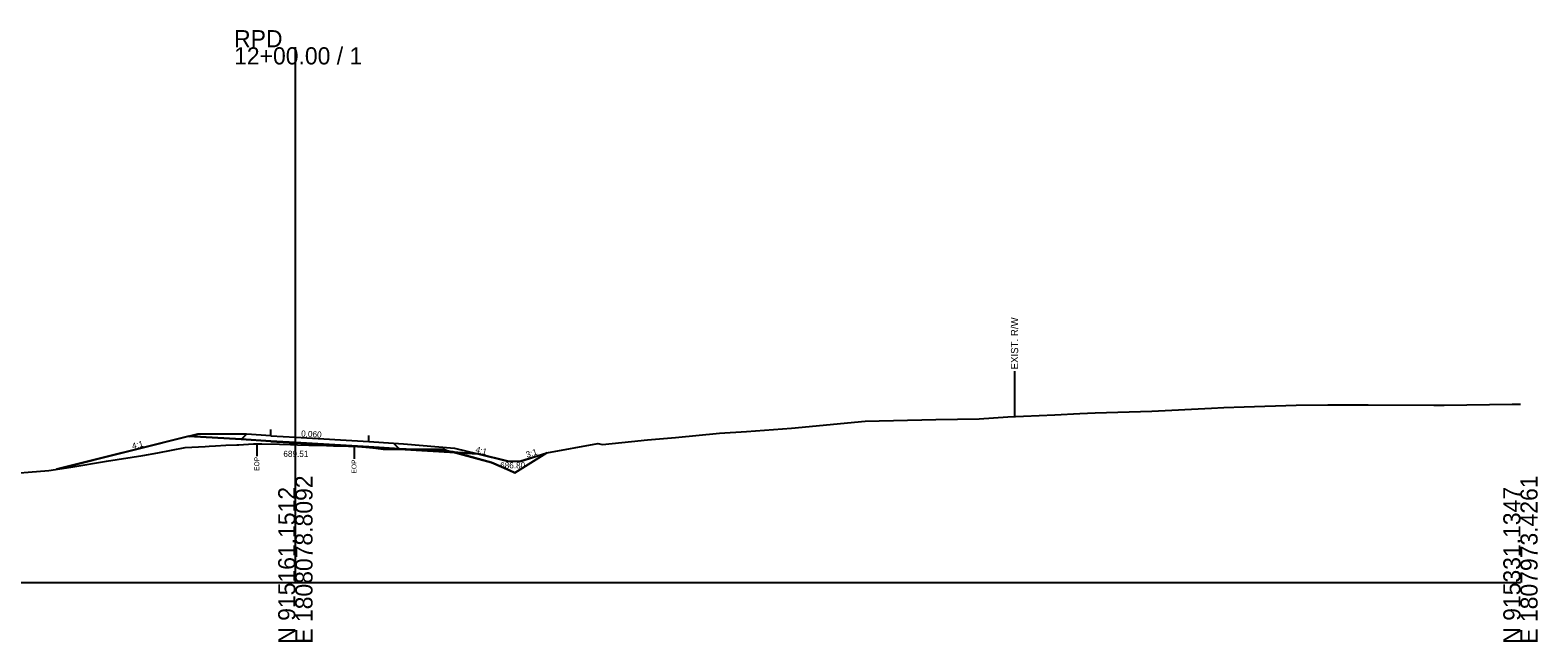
# Model space of a CAD drawing. Extents: x -26 to 403, y -10 to 8517.
# Drawn here: x 156.7 to 402.8, y 3990.3 to 4090.2 of the extents above; entities that cross this region are included whole.
import ezdxf

# ---------------------------------------------------------------- set-up
doc = ezdxf.new("R2010")
doc.units = 0
for name, color, linetype in [('Exist Cross Section Cell', 7, 'Continuous'), ('Exist XS Center Line Elevation Label', 7, 'Continuous'), ('Exist XS Ground Line', 7, 'Continuous'), ('Old_Level_10', 7, 'Continuous'), ('Prop XS Ditch Standard Text', 7, 'Continuous'), ('Prop XS Earthwork Shape', 7, 'Continuous'), ('Prop XS EOT Tick Mark', 7, 'Continuous'), ('Prop XS Finish Grade', 7, 'Continuous'), ('Prop XS Finish Grade Earthwork', 7, 'Continuous'), ('Prop XS Finish Grade Paved Shoulder', 7, 'Continuous'), ('Prop XS Finish Grade Pavement', 7, 'Continuous'), ('Prop XS Hydro Fill Slope Data', 7, 'Continuous'), ('Prop XS Pvmt Edge Slope', 7, 'Continuous'), ('Prop XS SE Text', 7, 'Continuous'), ('Prop XS Side Slope Text', 7, 'Continuous'), ('Prop XS Subgrade Earthwork', 7, 'Continuous')]:
    doc.layers.add(name, color=color, linetype=linetype)

msp = doc.modelspace()

# ---------------------------------------------------------------- linework, layer by layer
at = {"layer": 'Exist Cross Section Cell'}
for p, q in [((200, 4000), (200, 4087.4)), ((0, 4000), (200, 4000)), ((200, 4000), (400, 4000))]:
    msp.add_line(p, q, dxfattribs=at)
at = {"layer": 'Exist XS Ground Line'}
msp.add_lwpolyline([(151.58, 4017.62), (159.78, 4018.31), (163.35, 4018.86), (169.16, 4019.8), (175.11, 4020.72), (177.56, 4021.18), (182.03, 4022.05), (185.28, 4022.23), (185.95, 4022.26), (186.95, 4022.31), (188.64, 4022.4), (190.42, 4022.5), (190.76, 4022.5), (191.53, 4022.52), (193.18, 4022.62), (193.71, 4022.67), (194.5, 4022.64), (197.42, 4022.57), (199.23, 4022.53), (200, 4022.51), (200.36, 4022.5), (202.22, 4022.45), (203.55, 4022.42), (203.95, 4022.41), (206.24, 4022.34), (208.69, 4022.26), (209.21, 4022.25), (209.58, 4022.24), (210.24, 4022.19), (212.13, 4022.05), (213.16, 4021.93), (214.32, 4021.76), (217.56, 4021.77), (219.88, 4021.77), (224.28, 4021.77), (224.8, 4021.56), (232, 4019.59), (234.91, 4018.34), (235.82, 4017.9), (241.07, 4021.16), (249.38, 4022.69), (250.14, 4022.55), (254.86, 4023.04), (257.47, 4023.31), (262.04, 4023.69), (269.24, 4024.39), (273.65, 4024.68), (281.01, 4025.21), (293, 4026.32), (304.54, 4026.6), (311.61, 4026.74), (316.3, 4027.04), (323.96, 4027.38), (328.07, 4027.6), (330.59, 4027.7), (339.84, 4028), (349.57, 4028.48), (351.6, 4028.58), (354.92, 4028.69), (363.37, 4028.94), (368.55, 4029.03), (375.13, 4029.03), (385.88, 4028.97), (386.9, 4028.97), (387.52, 4028.98), (398.66, 4029.1), (400, 4029.13)], dxfattribs=at)
at = {"layer": 'Old_Level_10'}
for p, q in [((317.41, 4034.49), (317.41, 4027.09)), ((193.71, 4022.67), (193.71, 4020.62)), ((209.58, 4022.24), (209.58, 4020.19))]:
    msp.add_line(p, q, dxfattribs=at)
at = {"layer": 'Prop XS Earthwork Shape'}
for points in [[(182.59, 4023.9), (160.99, 4018.5), (163.35, 4018.86), (169.16, 4019.8), (175.11, 4020.72), (177.56, 4021.18), (182.03, 4022.05), (185.28, 4022.23), (185.95, 4022.26), (186.95, 4022.31), (188.64, 4022.4), (190.42, 4022.5), (190.76, 4022.5), (191.53, 4022.52), (193.18, 4022.62), (193.71, 4022.67), (194.5, 4022.64), (197.42, 4022.57), (199.23, 4022.53), (200, 4022.51), (200.36, 4022.5), (202.22, 4022.45), (203.55, 4022.42), (203.95, 4022.41), (206.24, 4022.34), (208.69, 4022.26), (209.21, 4022.25), (209.58, 4022.24), (210.24, 4022.19), (212.13, 4022.05), (213.16, 4021.93), (214.32, 4021.76), (217.56, 4021.77), (218.1, 4021.77), (216.98, 4021.83), (211.98, 4022.13), (199.98, 4022.85), (195.98, 4023.09), (191.13, 4023.38)], [(218.1, 4021.77), (219.88, 4021.77), (224.28, 4021.77), (224.8, 4021.56), (225.73, 4021.31)], [(225.73, 4021.31), (229.78, 4021.07), (234.84, 4019.8), (236.84, 4019.8), (241.07, 4021.16), (235.82, 4017.9), (234.91, 4018.34), (232, 4019.59)]]:
    msp.add_lwpolyline(points, close=True, dxfattribs=at)
at = {"layer": 'Prop XS EOT Tick Mark'}
for p, q in [((196, 4023.96), (196, 4024.96)), ((212, 4023), (212, 4024))]:
    msp.add_line(p, q, dxfattribs=at)
at = {"layer": 'Prop XS Finish Grade'}
for p, q in [((182.59, 4023.85), (184, 4024.2)), ((184, 4024.2), (184, 4024.2)), ((190.43, 4024.2), (184, 4024.2)), ((192, 4024.2), (190.43, 4024.2)), ((216, 4022.76), (217.64, 4022.63)), ((217.64, 4022.63), (226, 4021.96)), ((226, 4021.96), (226, 4021.96)), ((226, 4021.96), (229.78, 4021.02))]:
    msp.add_line(p, q, dxfattribs=at)
at = {"layer": 'Prop XS Finish Grade Earthwork'}
for p, q in [((172.5, 4021.33), (161.47, 4018.57)), ((229.78, 4021.02), (234.65, 4019.8)), ((234.65, 4019.8), (236.66, 4019.8)), ((236.66, 4019.8), (241.07, 4021.16))]:
    msp.add_line(p, q, dxfattribs=at)
at = {"layer": 'Prop XS Finish Grade Paved Shoulder'}
for p, q in [((196, 4023.96), (192, 4024.2)), ((212, 4023), (216, 4022.76))]:
    msp.add_line(p, q, dxfattribs=at)
at = {"layer": 'Prop XS Finish Grade Pavement'}
for p, q in [((196, 4023.96), (200, 4023.72)), ((200, 4023.72), (212, 4023))]:
    msp.add_line(p, q, dxfattribs=at)
at = {"layer": 'Prop XS Hydro Fill Slope Data'}
msp.add_line((184, 4024.2), (161.47, 4018.57), dxfattribs=at)
at = {"layer": 'Prop XS Pvmt Edge Slope'}
for p, q in [((192, 4024.2), (191.13, 4023.34)), ((216, 4022.76), (216.98, 4021.79))]:
    msp.add_line(p, q, dxfattribs=at)
at = {"layer": 'Prop XS Subgrade Earthwork'}
for p, q in [((191.13, 4023.34), (182.59, 4023.85)), ((195.98, 4023.05), (191.13, 4023.34)), ((195.98, 4023.05), (199.98, 4022.81)), ((199.98, 4022.81), (211.98, 4022.09)), ((211.98, 4022.09), (216.98, 4021.79)), ((216.98, 4021.79), (229.78, 4021.02))]:
    msp.add_line(p, q, dxfattribs=at)

# ---------------------------------------------------------------- texts
at = {"layer": 'Exist Cross Section Cell'}
for s, p in [('RPD', (190, 4087.4)), ('12+00.00 / 1', (190, 4084.6))]:
    msp.add_text(s, height=2.8, dxfattribs=at).set_placement(p)
for s, p in [('E 1808078.8092', (202.8, 3990)), ('E 1807973.4261', (402.8, 3990)), ('N 915161.1512', (200, 3990)), ('N 915331.1347', (400, 3990))]:
    msp.add_text(s, height=2.8, rotation=90, dxfattribs=at).set_placement(p)
at = {"layer": 'Exist XS Center Line Elevation Label'}
msp.add_text('689.51', height=1, dxfattribs=at).set_placement((198.04, 4020.51))
at = {"layer": 'Old_Level_10'}
for s, height, rotation, p in [('EXIST. R/W', 1.181, 90, (318, 4034.79)), ('EOP', 0.787, 90, (194.1, 4018.22)), ('EOP', 0.787, 90, (209.97, 4017.79)), ('3:1', 1, 18.4349, (237.83, 4020.35))]:
    msp.add_text(s, height=height, rotation=rotation, dxfattribs=at).set_placement(p)
at = {"layer": 'Prop XS Ditch Standard Text'}
msp.add_text('686.80', height=1, dxfattribs=at).set_placement((233.43, 4018.63))
at = {"layer": 'Prop XS SE Text'}
msp.add_text('0.060', height=1, rotation=356.5664, dxfattribs=at).set_placement((200.92, 4023.84))
at = {"layer": 'Prop XS Side Slope Text'}
for rotation, p in [(14.0362, (173.46, 4021.77)), (345.9638, (229.33, 4021.27))]:
    msp.add_text('4:1', height=1, rotation=rotation, dxfattribs=at).set_placement(p)

doc.saveas('drawing.dxf')
